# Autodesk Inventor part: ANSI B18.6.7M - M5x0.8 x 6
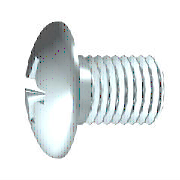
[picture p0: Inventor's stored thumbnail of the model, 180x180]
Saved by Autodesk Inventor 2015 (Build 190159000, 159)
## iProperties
Created: 2014-02
Part Number: ANSI B18.6.7M - M5x0.8 x 6
Material: Steel, Mild
Description: Cross Recessed Pan Head Machine Screw - Type I - Metric
Document SubType Name: Modeling
Standard: ANSI B18.6.7M
Designer: rsheridan
Standard Revision: 2005
Standards Organization: ANSI
Language: en-US
Size Designation: M5x0.8 x 6
Categories: <MemberInstance><Categories><Category DisplayName="Fasteners" InternalName="e4da775c-781d-43d5-af7c-5136215cf5a6" Mnemonic="FSTN"><Category DisplayName="Bolts"
Density: 1 g/cm^3
Appearance: Semi-Polished
IsCustomPart: 1
Author: rsheridan
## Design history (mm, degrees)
body "Solid1"
sketch "Sketch1"
  geometry: L1 (-5.739, 0)-(7.957, 0) reference; L2 (0, -0.961)-(0, 5.764) reference; L3 (6, 0)-(6, 2.5); L4 (6, 2.5)-(0.8, 2.5); L5 (-3.7, 4.75)-(-3.7, 0); L6 (-3.367, 2.284)-(-1.118, 1.163); L7 (-1.118, 1.163)-(-0.5, 0); L8 (-0.5, 0)-(6, 0); L9 (-3.367, 2.284)-(-3.7, 2.45); L10 (-2.137, 4.75)-(-3.7, 4.75); L11 (-3.7, 0)-(-3.7, 4.75); L12 (-2.137, 4.75)-(0, 4.75); L13 (0, 2.5)-(0.309, 2.5); L14 (0.309, 2.5)-(0.8, 2.5); L15 (0, 2.5)-(0, 4.75); L16 (0.8, 2.5)-(0, 2.5); A1 r 8 centre (4.3, 0) between (-2.137, 4.75) and (-3.367, 2.284); A2 r 8 centre (4.3, 0) between (-3.367, 2.284) and (-3.7, 0)
  constraints: 28 end point, 5 collinear, 4 perpendicular, 4 point on circle, 3 parallel, 3 point on line, 2 centre point, 1 coincident, 1 tangent
  dimensions: "d1" = 5 diameter of L4 L8 (= GD); "d2" = 3.2 distance from line of L7.end L5 (= INTI); "d12" = 62 deg angle of L7 L8; "d13" = 26.5 deg angle of L6 L8; "d16" = 4.9 diameter of L9.end L8 (= SDM); "d21" = 5 diameter of L13 L8 (= BDM); "d22" = 5.2 distance of L3.end L4.end (= GEL); "d23" = 0.49076 distance of L13.end L4.end (= GAL); "d24" = 3.7 distance between parallel lines of L5 L15 (= KOH); "d25" = 8 radius of A1 (= KR); "d29" = 9.5 diameter of L10 L8 (= KOD); "d30" = 6 distance between parallel lines of L3 L15 (= NLG)
revolve "Body" stored, may be unused: angle "d15" = 90 deg
node "Workplane"
sketch "Sketch2"
  geometry: L1 (-6.884, 0)-(8.057, 0) reference; L2 (0, -6.884)-(0, 8.057) reference; L3 (0, 2.45)-(0, 0); L4 (0, 0)-(2.45, 0); L5 (0, 0)-(5.922, 5.922); L6 (2.398, 0.5)-(1.168, 0.369); L7 (0.5, 2.398)-(0.369, 1.168); L8 (0.443, 0.686)-(0.443, 0.684); L9 (0.5, -2.398)-(0.369, -1.168); L10 (2.398, -0.5)-(1.168, -0.369); L11 (-0.5, 2.398)-(-0.369, 1.168); L12 (-2.398, 0.5)-(-1.168, 0.369); L13 (-2.398, -0.5)-(-1.168, -0.369); L14 (-0.5, -2.398)-(-0.369, -1.168); C1 r 4.75 at (0, 0) reference; A1 r 0.817 centre (0, 0) between (0.817, 0) and (0, 0.817); A2 r 2.45 centre (0, 0) between (2.45, 0) and (2.398, 0.5); A3 r 2.45 centre (0, 0) between (0.5, 2.398) and (0, 2.45); A4 r 2.45 centre (0, 0) between (2.398, 0.5) and (0.5, 2.398); A5 r 2.45 centre (0, 0) between (0, -2.45) and (0.5, -2.398); A6 r 2.45 centre (0, 0) between (0.5, -2.398) and (2.398, -0.5); A7 r 2.45 centre (0, 0) between (2.398, -0.5) and (2.45, 0); A8 r 2.45 centre (0, 0) between (0, 2.45) and (-0.5, 2.398); A9 r 2.45 centre (0, 0) between (-0.5, 2.398) and (-2.398, 0.5); A10 r 2.45 centre (0, 0) between (-2.398, 0.5) and (-2.45, 0); A11 r 2.45 centre (0, 0) between (-2.45, 0) and (-2.398, -0.5); A12 r 2.45 centre (0, 0) between (-2.398, -0.5) and (-0.5, -2.398); A13 r 2.45 centre (0, 0) between (-0.5, -2.398) and (0, -2.45); A14 r 1.225 centre (0, 0) between (1.214, 0.165) and (0, 1.225); A15 r 0.726 centre (1.091, 1.091) between (0.369, 1.168) and (1.168, 0.369); A16 r 0.726 centre (1.091, -1.091) between (1.168, -0.369) and (0.369, -1.168); A17 r 2.45 centre (0, 0) between (2.398, -0.5) and (2.45, 0); A18 r 2.45 centre (0, 0) between (0.5, -2.398) and (2.398, -0.5); A19 r 2.45 centre (0, 0) between (0, -2.45) and (0.5, -2.398); A20 r 2.45 centre (0, 0) between (-0.5, -2.398) and (0, -2.45); A21 r 2.45 centre (0, 0) between (-2.398, -0.5) and (-0.5, -2.398); A22 r 2.45 centre (0, 0) between (-2.45, 0) and (-2.398, -0.5); A23 r 2.45 centre (0, 0) between (-2.398, 0.5) and (-2.45, 0); A24 r 2.45 centre (0, 0) between (-0.5, 2.398) and (-2.398, 0.5); A25 r 2.45 centre (0, 0) between (0, 2.45) and (-0.5, 2.398); A26 r 0.726 centre (-1.091, 1.091) between (-1.168, 0.369) and (-0.369, 1.168); A27 r 0.726 centre (-1.091, -1.091) between (-0.369, -1.168) and (-1.168, -0.369)
  constraints: 57 point on circle, 27 centre point, 24 end point, 18 symmetric about line, 4 coincident, 3 collinear, 3 tangent, 2 point on line, 1 midpoint, 1 perpendicular, 27 other
  dimensions: "d4" = 45 deg angle of L5 L4; "d5" = 1.63333 diameter of A1 (= 0.333333 x SDM); "d6" = 4.9 diameter of A4 (= SDM); "d7" = 0.5 distance from line of L7.start L3 (= 0.5 x SBR); "d17" = 2.45 diameter of A14 (= 0.5 x SDM)
extrude "Slot" join sketch "Sketch2" taper "d18" = 5 deg; stored distance "d52" = 10
revolve "Cut" stored, may be unused: angle "d54" = 90 deg
fillet "Fillet1" dims "d19" = 0.2 (= 0.2 x SBR)
feature "Thread" dims "d8" = 5.2 (= GEL), "d9" = 0
fillet "Fillet2" dims "d27" = 1.6 (= KKR)
fillet "Fillet3" dims "d74" = 0.2 (= R)
other parameters: "GD" = 5 (= NND) [user parameter; used in 1 equation term], "NLG" = 6 [user parameter; used in 1 equation term], "GEL" = 5.2 [user parameter; used in 2 equation terms], "KOD" = 9.5 [user parameter; used in 1 equation term], "KOH" = 3.7 [user parameter; used in 2 equation terms], "SDM" = 4.9 [user parameter; used in 4 equation terms], "INTI" = 3.2 [user parameter; used in 1 equation term], "SBR" = 1 [user parameter; used in 2 equation terms], "d3" = -3.7 (= -KOH), "d20" = 0, "GAL" = 0.49076 (= 0.61345 x PTC) [user parameter; used in 1 equation term], "BDM" = 5 (= NND) [user parameter; used in 1 equation term], "KR" = 8 [user parameter; used in 1 equation term], "KKR" = 1.6 [user parameter; used in 1 equation term], "d72" = 0, "d73" = 0, "R" = 0.2 [user parameter; used in 1 equation term], "SPD" = 3.6 [user parameter], "THREADDIA" = 5 [user parameter; used in 1 equation term], "TPU" = 12.5 (computed from PTC) [user parameter], "PTC" = 0.8 [user parameter; used in 4 equation terms], "NND" = 5 [user parameter; used in 2 equation terms], "GUL" = 0.49076 (= 0.61345 x PTC) [user parameter], "TOA" = 30 deg [user parameter], "GD1" = 4.01848 (= THREADDIA - 1.2269 x PTC) [user parameter]
